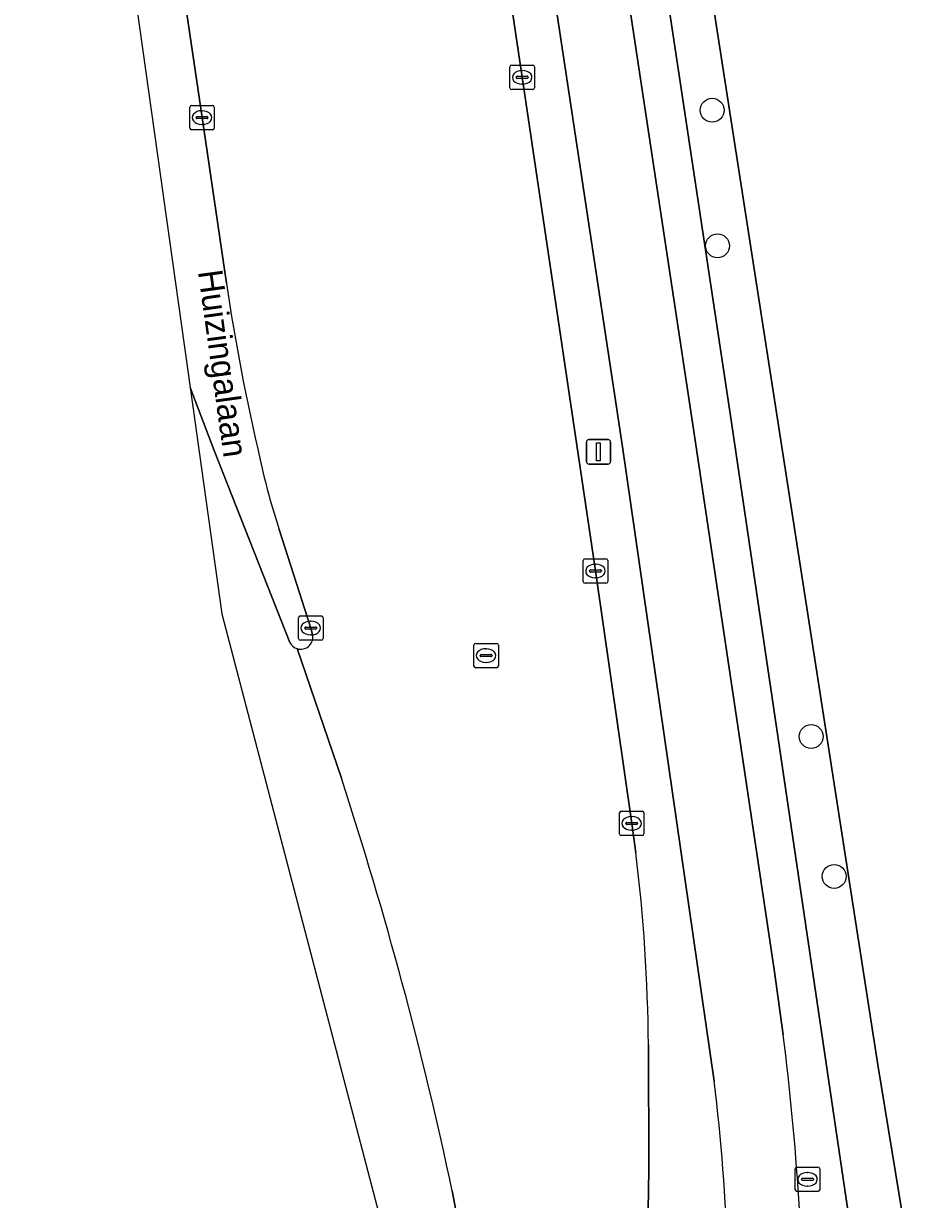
# Model space of a CAD drawing. Extents: x 159451 to 160664, y 388402 to 389723.
# Drawn here: x 159481.68 to 159518.14, y 388994.49 to 389042.63 of the extents above; entities that cross this region are included whole.
import ezdxf

# ---------------------------------------------------------------- set-up
doc = ezdxf.new("R2010")
doc.units = 0
for name, color, linetype in [('IMGEO_Berm_groen', 7, 'Continuous'), ('IMGEO_Boom', 7, 'Continuous'), ('IMGEO_Brandkraan', 7, 'Continuous'), ('IMGEO_Fietspad_gesloten', 7, 'Continuous'), ('IMGEO_Gemengd_bos', 7, 'Continuous'), ('IMGEO_Groenvoorziening', 7, 'Continuous'), ('IMGEO_Hek', 7, 'Continuous'), ('IMGEO_Kolk', 7, 'Continuous'), ('IMGEO_Lichtmast', 7, 'Continuous'), ('IMGEO_Openbare_ruimte_label', 7, 'Continuous'), ('IMGEO_OVBaan_gesloten', 7, 'Continuous'), ('IMGEO_Rijbaan_regionaal_gesloten', 7, 'Continuous'), ('IMGEO_Rioolput', 7, 'Continuous'), ('IMGEO_Voetpad_open', 7, 'Continuous')]:
    doc.layers.add(name, color=color, linetype=linetype)

msp = doc.modelspace()

# ---------------------------------------------------------------- linework, layer by layer
at = {"layer": 'IMGEO_Berm_groen'}
for points in [[(159496.535, 389078.187), (159496.731, 389076.306), (159497.993, 389067.961), (159499.086, 389060.633), (159502.09, 389040.43), (159505.089, 389020.22), (159506.573, 389009.887), (159506.742, 389008.683)], [(159509.943, 388999.337), (159506.196, 389025.302), (159500.421, 389063.479), (159498.535, 389077.37), (159498.641, 389077.39), (159498.527, 389078.497)], [(159482.942, 389076.468), (159481.685, 389076.274), (159488.502, 389027.728)], [(159489.988, 389032), (159488.99, 389038.781), (159486.154, 389057.989), (159483.743, 389074.245), (159483.459, 389076.149)], [(159488.502, 389027.728), (159489.48, 389025.155), (159492.585, 389017.295)], [(159493.524, 389017.562), (159493.44, 389017.883), (159492.144, 389021.922)], [(159507.254, 389000.815), (159507.271, 388995.718), (159507.209, 388991.509), (159506.882, 388978.092), (159506.819, 388973.728)]]:
    msp.add_lwpolyline(points, dxfattribs=at)
for centre, radius, start, end in [((159576.305, 389044.767), 87.256, 188.41335, 193.24774), ((159520.115, 389031.041), 29.42, 192.3045, 198.056), ((159493.03, 389017.515), 0.497, 252.6926, 5.4279), ((159493.024, 389017.508), 0.488, 205.8838, 253.0408), ((159436.93, 389000.189), 70.327, 0.5097, 6.9367), ((159438.669, 388990.338), 71.84, 1.4124, 7.19586)]:
    msp.add_arc(centre, radius, start, end, dxfattribs=at)
at = {"layer": 'IMGEO_Boom'}
for centre in [(159509.863, 389039.082), (159510.083, 389033.53), (159513.916, 389013.444), (159514.857, 389007.717)]:
    msp.add_circle(centre, 0.489, dxfattribs=at)
at = {"layer": 'IMGEO_Brandkraan'}
for p, q in [((159513.265, 388994.89), (159513.265, 388995.742)), ((159513.34, 388995.816), (159514.192, 388995.816)), ((159514.266, 388995.742), (159514.266, 388994.89)), ((159513.524, 388995.31), (159513.524, 388995.322)), ((159513.962, 388995.273), (159513.564, 388995.273)), ((159513.567, 388995.359), (159513.965, 388995.359)), ((159513.753, 388995.596), (159513.778, 388995.596)), ((159514.008, 388995.322), (159514.008, 388995.31)), ((159514.192, 388994.816), (159513.34, 388994.816)), ((159513.776, 388995.036), (159513.751, 388995.036))]:
    msp.add_line(p, q, dxfattribs=at)
for points in [[(159513.265, 388994.89), (159513.265, 388995.742)], [(159513.34, 388995.816), (159514.192, 388995.816)], [(159514.266, 388995.742), (159514.266, 388994.89)], [(159514.192, 388994.816), (159513.34, 388994.816)]]:
    msp.add_lwpolyline(points, dxfattribs=at)
for centre, radius, start, end in [((159513.342, 388995.74), 0.0765, 91.552, 178.448), ((159513.342, 388995.74), 0.0765, 91.552, 178.448), ((159514.19, 388995.74), 0.0765, 1.552, 88.448), ((159514.19, 388995.74), 0.0765, 1.552, 88.448), ((159513.564, 388995.319), 0.0403, 85.8775, 175.7526), ((159513.561, 388995.309), 0.0366, 178.938, 274.7102), ((159513.965, 388995.316), 0.043, 264.8664, 352.4533), ((159513.969, 388995.321), 0.0386, 1.7309, 96.639), ((159513.342, 388994.892), 0.0765, 181.552, 268.448), ((159513.342, 388994.892), 0.0765, 181.552, 268.448), ((159514.19, 388994.892), 0.0765, 271.552, 358.448), ((159514.19, 388994.892), 0.0765, 271.552, 358.448)]:
    msp.add_arc(centre, radius, start, end, dxfattribs=at)
for centre, major_axis, ratio, start_param, end_param in [((159513.752, 388995.316), (-0.387, 0.002), 0.722429, 4.712389, 7.853982), ((159513.777, 388995.316), (-0.39, 0.002), 0.717154, 1.570796, 4.712389)]:
    msp.add_ellipse(centre, major_axis=major_axis, ratio=ratio, start_param=start_param, end_param=end_param, dxfattribs=at)
at = {"layer": 'IMGEO_Fietspad_gesloten'}
msp.add_lwpolyline([(159512.775, 389001.232), (159512.419, 389003.812), (159509.105, 389026.02), (159503.37, 389063.924), (159501.365, 389077.519), (159498.641, 389077.39), (159498.535, 389077.37), (159500.421, 389063.479), (159506.196, 389025.302), (159509.943, 388999.337)], dxfattribs=at)
for centre, radius, start, end in [((159405.559, 388987.753), 108.06, 0.01241, 7.16571), ((159438.669, 388990.338), 71.84, 1.4124, 7.19586)]:
    msp.add_arc(centre, radius, start, end, dxfattribs=at)
at = {"layer": 'IMGEO_Gemengd_bos'}
msp.add_lwpolyline([(159543.984, 388938.777), (159539.1, 388937.88), (159514.559, 389071.891), (159519.41, 389072.798), (159518.574, 389077.364), (159573.514, 389087.444), (159575.636, 389087.806), (159574.696, 389093.295), (159556.654, 389090.594), (159543.414, 389088.835), (159534.923, 389087.144), (159506.995, 389079.727), (159505.308, 389078.139), (159504.909, 389075.552), (159516.649, 389000), (159527.326, 388934.886), (159532.821, 388904.1), (159538.108, 388877.879), (159538.123, 388877.804), (159546.646, 388879.386), (159542.832, 388899.409), (159576.655, 388905.852), (159575.832, 388910.173)], dxfattribs=at)
at = {"layer": 'IMGEO_Groenvoorziening'}
for points in [[(159516.649, 389000), (159504.909, 389075.552), (159505.308, 389078.139), (159506.995, 389079.727), (159534.923, 389087.144), (159543.414, 389088.835), (159556.654, 389090.594), (159574.696, 389093.295), (159575.636, 389087.806), (159616.622, 389094.8), (159617.368, 389090.768), (159624.202, 389092.026), (159623.295, 389096.867), (159619.743, 389102.132), (159610.539, 389099.965), (159603.075, 389098.713), (159550.307, 389091.495), (159531.415, 389088.058), (159524.658, 389086.444), (159511.437, 389082.946), (159506.072, 389081.377)], [(159503.082, 389076.792), (159504.945, 389064.234), (159510.601, 389026.663), (159515.653, 388992.482), (159516.512, 388985.346), (159517.252, 388980.028), (159520.19, 388962.941), (159524.008, 388940.78), (159527.88, 388918.773), (159530.761, 388903.029), (159535.59, 388877.415), (159538.108, 388877.879), (159532.821, 388904.1), (159527.326, 388934.886), (159516.649, 389000)]]:
    msp.add_lwpolyline(points, dxfattribs=at)
at = {"layer": 'IMGEO_Hek'}
msp.add_lwpolyline([(159678.25, 388782.74), (159562.528, 388756.756), (159538.536, 388875.752), (159538.123, 388877.804), (159532.821, 388904.1), (159527.326, 388934.886), (159516.649, 389000), (159504.909, 389075.552), (159505.308, 389078.139), (159506.995, 389079.727), (159534.923, 389087.144), (159543.414, 389088.835), (159556.654, 389090.594), (159574.696, 389093.295)], dxfattribs=at)
at = {"layer": 'IMGEO_Kolk'}
for p, q in [((159501.589, 389040.004), (159501.589, 389040.856)), ((159501.664, 389040.93), (159502.516, 389040.93)), ((159502.077, 389040.71), (159502.102, 389040.71)), ((159502.59, 389040.856), (159502.59, 389040.004)), ((159501.848, 389040.424), (159501.848, 389040.436)), ((159502.286, 389040.387), (159501.888, 389040.387)), ((159501.891, 389040.473), (159502.289, 389040.473)), ((159502.1, 389040.15), (159502.075, 389040.15)), ((159502.332, 389040.436), (159502.332, 389040.424)), ((159502.516, 389039.93), (159501.664, 389039.93)), ((159488.489, 389038.355), (159488.489, 389039.207)), ((159488.564, 389039.281), (159489.416, 389039.281)), ((159488.977, 389039.061), (159489.002, 389039.061)), ((159489.49, 389039.207), (159489.49, 389038.355)), ((159488.748, 389038.775), (159488.748, 389038.787)), ((159489.186, 389038.738), (159488.788, 389038.738)), ((159488.791, 389038.824), (159489.189, 389038.824)), ((159489.232, 389038.787), (159489.232, 389038.775)), ((159489.416, 389038.281), (159488.564, 389038.281)), ((159489, 389038.501), (159488.975, 389038.501)), ((159504.588, 389019.794), (159504.588, 389020.646)), ((159504.663, 389020.72), (159505.515, 389020.72)), ((159505.076, 389020.5), (159505.101, 389020.5)), ((159505.589, 389020.646), (159505.589, 389019.794)), ((159504.847, 389020.214), (159504.847, 389020.226)), ((159505.285, 389020.177), (159504.887, 389020.177)), ((159504.89, 389020.263), (159505.288, 389020.263)), ((159505.099, 389019.94), (159505.074, 389019.94)), ((159505.331, 389020.226), (159505.331, 389020.214)), ((159505.515, 389019.72), (159504.663, 389019.72)), ((159493.014, 389018.383), (159493.866, 389018.383)), ((159492.939, 389017.457), (159492.939, 389018.309)), ((159493.198, 389017.877), (159493.198, 389017.889)), ((159493.241, 389017.926), (159493.639, 389017.926)), ((159493.427, 389018.163), (159493.452, 389018.163)), ((159493.682, 389017.889), (159493.682, 389017.877)), ((159493.94, 389018.309), (159493.94, 389017.457)), ((159493.636, 389017.84), (159493.238, 389017.84)), ((159493.45, 389017.603), (159493.425, 389017.603)), ((159493.866, 389017.383), (159493.014, 389017.383)), ((159506.072, 389009.461), (159506.072, 389010.313)), ((159506.147, 389010.387), (159506.999, 389010.387)), ((159507.073, 389010.313), (159507.073, 389009.461)), ((159506.331, 389009.881), (159506.331, 389009.893)), ((159506.769, 389009.844), (159506.371, 389009.844)), ((159506.374, 389009.93), (159506.772, 389009.93)), ((159506.56, 389010.167), (159506.585, 389010.167)), ((159506.815, 389009.893), (159506.815, 389009.881)), ((159506.999, 389009.387), (159506.147, 389009.387)), ((159506.583, 389009.607), (159506.558, 389009.607))]:
    msp.add_line(p, q, dxfattribs=at)
for points in [[(159501.589, 389040.004), (159501.589, 389040.856)], [(159501.664, 389040.93), (159502.516, 389040.93)], [(159502.59, 389040.856), (159502.59, 389040.004)], [(159502.516, 389039.93), (159501.664, 389039.93)], [(159488.489, 389038.355), (159488.489, 389039.207)], [(159488.564, 389039.281), (159489.416, 389039.281)], [(159489.49, 389039.207), (159489.49, 389038.355)], [(159489.416, 389038.281), (159488.564, 389038.281)], [(159504.588, 389019.794), (159504.588, 389020.646)], [(159504.663, 389020.72), (159505.515, 389020.72)], [(159505.589, 389020.646), (159505.589, 389019.794)], [(159505.515, 389019.72), (159504.663, 389019.72)], [(159493.014, 389018.383), (159493.866, 389018.383)], [(159492.939, 389017.457), (159492.939, 389018.309)], [(159493.94, 389018.309), (159493.94, 389017.457)], [(159493.866, 389017.383), (159493.014, 389017.383)], [(159506.072, 389009.461), (159506.072, 389010.313)], [(159506.147, 389010.387), (159506.999, 389010.387)], [(159507.073, 389010.313), (159507.073, 389009.461)], [(159506.999, 389009.387), (159506.147, 389009.387)]]:
    msp.add_lwpolyline(points, dxfattribs=at)
for centre, radius, start, end in [((159501.666, 389040.854), 0.0765, 91.552, 178.448), ((159501.666, 389040.854), 0.0765, 91.552, 178.448), ((159502.514, 389040.854), 0.0765, 1.552, 88.448), ((159502.514, 389040.854), 0.0765, 1.552, 88.448), ((159501.888, 389040.433), 0.0403, 85.8775, 175.7526), ((159501.885, 389040.423), 0.0366, 178.938, 274.7102), ((159502.289, 389040.43), 0.043, 264.8664, 352.4533), ((159502.293, 389040.435), 0.0386, 1.7309, 96.639), ((159501.666, 389040.006), 0.0765, 181.552, 268.448), ((159501.666, 389040.006), 0.0765, 181.552, 268.448), ((159502.514, 389040.006), 0.0765, 271.552, 358.448), ((159502.514, 389040.006), 0.0765, 271.552, 358.448), ((159488.566, 389039.205), 0.0765, 91.552, 178.448), ((159488.566, 389039.205), 0.0765, 91.552, 178.448), ((159489.414, 389039.205), 0.0765, 1.552, 88.448), ((159489.414, 389039.205), 0.0765, 1.552, 88.448), ((159488.788, 389038.784), 0.0403, 85.8775, 175.7526), ((159488.785, 389038.774), 0.0366, 178.938, 274.7102), ((159489.189, 389038.781), 0.043, 264.8664, 352.4533), ((159489.193, 389038.786), 0.0386, 1.7309, 96.639), ((159488.566, 389038.357), 0.0765, 181.552, 268.448), ((159488.566, 389038.357), 0.0765, 181.552, 268.448), ((159489.414, 389038.357), 0.0765, 271.552, 358.448), ((159489.414, 389038.357), 0.0765, 271.552, 358.448), ((159504.665, 389020.644), 0.0765, 91.552, 178.448), ((159504.665, 389020.644), 0.0765, 91.552, 178.448), ((159505.513, 389020.644), 0.0765, 1.552, 88.448), ((159505.513, 389020.644), 0.0765, 1.552, 88.448), ((159504.887, 389020.223), 0.0403, 85.8775, 175.7526), ((159504.884, 389020.213), 0.0366, 178.938, 274.7102), ((159505.288, 389020.22), 0.043, 264.8664, 352.4533), ((159505.292, 389020.225), 0.0386, 1.7309, 96.639), ((159504.665, 389019.796), 0.0765, 181.552, 268.448), ((159504.665, 389019.796), 0.0765, 181.552, 268.448), ((159505.513, 389019.796), 0.0765, 271.552, 358.448), ((159505.513, 389019.796), 0.0765, 271.552, 358.448), ((159493.016, 389018.307), 0.0765, 91.552, 178.448), ((159493.016, 389018.307), 0.0765, 91.552, 178.448), ((159493.864, 389018.307), 0.0765, 1.552, 88.448), ((159493.864, 389018.307), 0.0765, 1.552, 88.448), ((159493.238, 389017.886), 0.0403, 85.8775, 175.7526), ((159493.643, 389017.888), 0.0386, 1.7309, 96.639), ((159493.016, 389017.459), 0.0765, 181.552, 268.448), ((159493.016, 389017.459), 0.0765, 181.552, 268.448), ((159493.235, 389017.876), 0.0366, 178.938, 274.7102), ((159493.639, 389017.883), 0.043, 264.8664, 352.4533), ((159493.864, 389017.459), 0.0765, 271.552, 358.448), ((159493.864, 389017.459), 0.0765, 271.552, 358.448), ((159506.149, 389010.311), 0.0765, 91.552, 178.448), ((159506.149, 389010.311), 0.0765, 91.552, 178.448), ((159506.997, 389010.311), 0.0765, 1.552, 88.448), ((159506.997, 389010.311), 0.0765, 1.552, 88.448), ((159506.371, 389009.89), 0.0403, 85.8775, 175.7526), ((159506.368, 389009.88), 0.0366, 178.938, 274.7102), ((159506.772, 389009.887), 0.043, 264.8664, 352.4533), ((159506.776, 389009.892), 0.0386, 1.7309, 96.639), ((159506.149, 389009.463), 0.0765, 181.552, 268.448), ((159506.149, 389009.463), 0.0765, 181.552, 268.448), ((159506.997, 389009.463), 0.0765, 271.552, 358.448), ((159506.997, 389009.463), 0.0765, 271.552, 358.448)]:
    msp.add_arc(centre, radius, start, end, dxfattribs=at)
for centre, major_axis, ratio, start_param, end_param in [((159502.076, 389040.43), (-0.387, 0.002), 0.722429, 4.712389, 7.853982), ((159502.101, 389040.43), (-0.39, 0.002), 0.717154, 1.570796, 4.712389), ((159488.976, 389038.781), (-0.387, 0.002), 0.722429, 4.712389, 7.853982), ((159489.001, 389038.781), (-0.39, 0.002), 0.717154, 1.570796, 4.712389), ((159505.075, 389020.22), (-0.387, 0.002), 0.722429, 4.712389, 7.853982), ((159505.1, 389020.22), (-0.39, 0.002), 0.717154, 1.570796, 4.712389), ((159493.426, 389017.883), (-0.387, 0.002), 0.722429, 4.712389, 7.853982), ((159493.451, 389017.883), (-0.39, 0.002), 0.717154, 1.570796, 4.712389), ((159506.559, 389009.887), (-0.387, 0.002), 0.722429, 4.712389, 7.853982), ((159506.584, 389009.887), (-0.39, 0.002), 0.717154, 1.570796, 4.712389)]:
    msp.add_ellipse(centre, major_axis=major_axis, ratio=ratio, start_param=start_param, end_param=end_param, dxfattribs=at)
at = {"layer": 'IMGEO_Lichtmast'}
for p, q in [((159504.817, 389025.598), (159505.607, 389025.598)), ((159505.607, 389025.598), (159504.817, 389025.598)), ((159504.717, 389024.698), (159504.717, 389025.498)), ((159504.717, 389025.498), (159504.717, 389024.698)), ((159505.707, 389025.498), (159505.707, 389024.698)), ((159505.707, 389024.698), (159505.707, 389025.498)), ((159505.607, 389024.598), (159504.817, 389024.598)), ((159504.817, 389024.598), (159505.607, 389024.598))]:
    msp.add_line(p, q, dxfattribs=at)
msp.add_lwpolyline([(159505.137, 389025.473), (159505.287, 389025.473), (159505.287, 389024.723), (159505.137, 389024.723), (159505.137, 389025.473)], dxfattribs=at)
for centre, start, end in [((159504.817, 389025.498), 90, 180), ((159504.817, 389025.498), 90, 180), ((159505.607, 389025.498), 0, 90), ((159505.607, 389025.498), 360, 90), ((159504.817, 389024.698), 180, 270), ((159504.817, 389024.698), 180, 270), ((159505.607, 389024.698), 270, 0), ((159505.607, 389024.698), 270, 0)]:
    msp.add_arc(centre, 0.1, start, end, dxfattribs=at)
at = {"layer": 'IMGEO_OVBaan_gesloten'}
for points in [[(159492.585, 389017.295), (159489.48, 389025.155), (159488.502, 389027.728), (159489.804, 389018.46), (159497.362, 388989.594), (159522.054, 388850.953), (159530.299, 388810.06), (159544.826, 388745.703)], [(159494.69, 389011.738), (159492.882, 389017.041)], [(159541.749, 388769.516), (159538.98, 388781.958), (159535.343, 388798.849), (159531.945, 388815.103), (159528.539, 388831.763), (159524.959, 388849.753), (159521.554, 388867.599), (159517.659, 388888.539), (159514.579, 388905.283), (159510.836, 388926.495), (159507.601, 388945.012), (159503.761, 388967.731), (159500.266, 388989.259), (159500.031, 388990.584), (159499.228, 388994.844)]]:
    msp.add_lwpolyline(points, dxfattribs=at)
for centre, radius, start, end in [((159493.024, 389017.508), 0.488, 205.8838, 253.0408), ((159336.91, 388960.299), 165.953, 12.01451, 18.05678)]:
    msp.add_arc(centre, radius, start, end, dxfattribs=at)
at = {"layer": 'IMGEO_Rijbaan_regionaal_gesloten'}
for points in [[(159506.742, 389008.683), (159506.573, 389009.887), (159505.089, 389020.22), (159502.09, 389040.43), (159499.086, 389060.633), (159497.993, 389067.961), (159496.731, 389076.306), (159496.535, 389078.187), (159496.506, 389078.538), (159496.505, 389079.28), (159496.581, 389079.932), (159496.744, 389080.843), (159496.955, 389081.738), (159496.741, 389081.707), (159482.68, 389079.493), (159482.497, 389079.455), (159483.05, 389077.74), (159483.459, 389076.149), (159483.743, 389074.245), (159486.154, 389057.989), (159488.99, 389038.781), (159489.988, 389032)], [(159492.144, 389021.922), (159493.44, 389017.883), (159493.524, 389017.562)], [(159492.882, 389017.041), (159494.69, 389011.738)], [(159506.819, 388973.728), (159506.882, 388978.092), (159507.209, 388991.509), (159507.271, 388995.718), (159507.254, 389000.815)], [(159499.228, 388994.844), (159500.031, 388990.584), (159500.266, 388989.259), (159503.761, 388967.731), (159507.601, 388945.012), (159510.836, 388926.495), (159514.579, 388905.283), (159517.659, 388888.539), (159521.554, 388867.599), (159524.959, 388849.753), (159528.539, 388831.763), (159531.945, 388815.103), (159535.343, 388798.849), (159538.98, 388781.958), (159541.749, 388769.516)]]:
    msp.add_lwpolyline(points, dxfattribs=at)
for centre, radius, start, end in [((159576.305, 389044.767), 87.256, 188.41335, 193.24774), ((159520.115, 389031.041), 29.42, 192.3045, 198.056), ((159493.03, 389017.515), 0.497, 252.6926, 5.4279), ((159336.91, 388960.299), 165.953, 12.01451, 18.05678), ((159436.93, 389000.189), 70.327, 0.5097, 6.9367)]:
    msp.add_arc(centre, radius, start, end, dxfattribs=at)
at = {"layer": 'IMGEO_Rioolput'}
for p, q in [((159500.113, 389016.33), (159500.113, 389017.182)), ((159500.188, 389017.256), (159501.04, 389017.256)), ((159500.601, 389017.036), (159500.626, 389017.036)), ((159501.114, 389017.182), (159501.114, 389016.33)), ((159500.372, 389016.75), (159500.372, 389016.762)), ((159500.81, 389016.713), (159500.412, 389016.713)), ((159500.415, 389016.799), (159500.813, 389016.799)), ((159500.624, 389016.476), (159500.599, 389016.476)), ((159500.856, 389016.762), (159500.856, 389016.75)), ((159501.04, 389016.256), (159500.188, 389016.256))]:
    msp.add_line(p, q, dxfattribs=at)
for points in [[(159500.113, 389016.33), (159500.113, 389017.182)], [(159500.188, 389017.256), (159501.04, 389017.256)], [(159501.114, 389017.182), (159501.114, 389016.33)], [(159501.04, 389016.256), (159500.188, 389016.256)]]:
    msp.add_lwpolyline(points, dxfattribs=at)
for centre, radius, start, end in [((159500.19, 389017.18), 0.0765, 91.552, 178.448), ((159500.19, 389017.18), 0.0765, 91.552, 178.448), ((159501.038, 389017.18), 0.0765, 1.552, 88.448), ((159501.038, 389017.18), 0.0765, 1.552, 88.448), ((159500.412, 389016.759), 0.0403, 85.8775, 175.7526), ((159500.409, 389016.749), 0.0366, 178.938, 274.7102), ((159500.813, 389016.756), 0.043, 264.8664, 352.4533), ((159500.817, 389016.761), 0.0386, 1.7309, 96.639), ((159500.19, 389016.332), 0.0765, 181.552, 268.448), ((159500.19, 389016.332), 0.0765, 181.552, 268.448), ((159501.038, 389016.332), 0.0765, 271.552, 358.448), ((159501.038, 389016.332), 0.0765, 271.552, 358.448)]:
    msp.add_arc(centre, radius, start, end, dxfattribs=at)
for centre, major_axis, ratio, start_param, end_param in [((159500.6, 389016.756), (-0.387, 0.002), 0.722429, 4.712389, 7.853982), ((159500.625, 389016.756), (-0.39, 0.002), 0.717154, 1.570796, 4.712389)]:
    msp.add_ellipse(centre, major_axis=major_axis, ratio=ratio, start_param=start_param, end_param=end_param, dxfattribs=at)
at = {"layer": 'IMGEO_Voetpad_open'}
for points in [[(159501.365, 389077.519), (159503.37, 389063.924), (159509.105, 389026.02), (159512.419, 389003.812), (159512.775, 389001.232)], [(159538.421, 388862.689), (159536.009, 388875.199), (159538.553, 388875.669), (159538.536, 388875.752), (159547.047, 388877.281), (159546.646, 388879.386), (159538.123, 388877.804), (159538.108, 388877.879), (159535.59, 388877.415), (159530.761, 388903.029), (159527.88, 388918.773), (159524.008, 388940.78), (159520.19, 388962.941), (159517.252, 388980.028), (159516.512, 388985.346), (159515.653, 388992.482), (159510.601, 389026.663), (159504.945, 389064.234), (159503.082, 389076.792)]]:
    msp.add_lwpolyline(points, dxfattribs=at)
msp.add_arc((159405.559, 388987.753), 108.06, 0.01241, 7.16571, dxfattribs=at)

# ---------------------------------------------------------------- texts
at = {"layer": 'IMGEO_Openbare_ruimte_label'}
msp.add_text('Huizingalaan', height=1, rotation=277.8709, dxfattribs=at).set_placement((159488.821, 389032.483))

doc.saveas('drawing.dxf')
